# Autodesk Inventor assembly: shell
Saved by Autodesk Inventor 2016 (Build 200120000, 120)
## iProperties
Created: 2018-05
Part Number: shell
Document SubType Name: Assembly
Designer: Administrator
Title: shell
Author: Administrator
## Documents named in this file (4)
- c:\worker\convert-fusion-mar-2018\tmp\job-1\16\output\files\8c58ff39-88bb-4352-afd9-60265520bae5\shell_1.iam
- c:\worker\convert-fusion-mar-2018\tmp\job-1\16\output\files\8c58ff39-88bb-4352-afd9-60265520bae5\outer.ipt
- c:\worker\convert-fusion-mar-2018\tmp\job-1\16\output\files\8c58ff39-88bb-4352-afd9-60265520bae5\back_shell.ipt
- c:\worker\convert-fusion-mar-2018\tmp\job-1\16\output\files\8c58ff39-88bb-4352-afd9-60265520bae5\mid_cover.ipt
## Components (3 placed, 3 different names)
1. outer:1
2. back_shell:1
3. mid_cover:1
